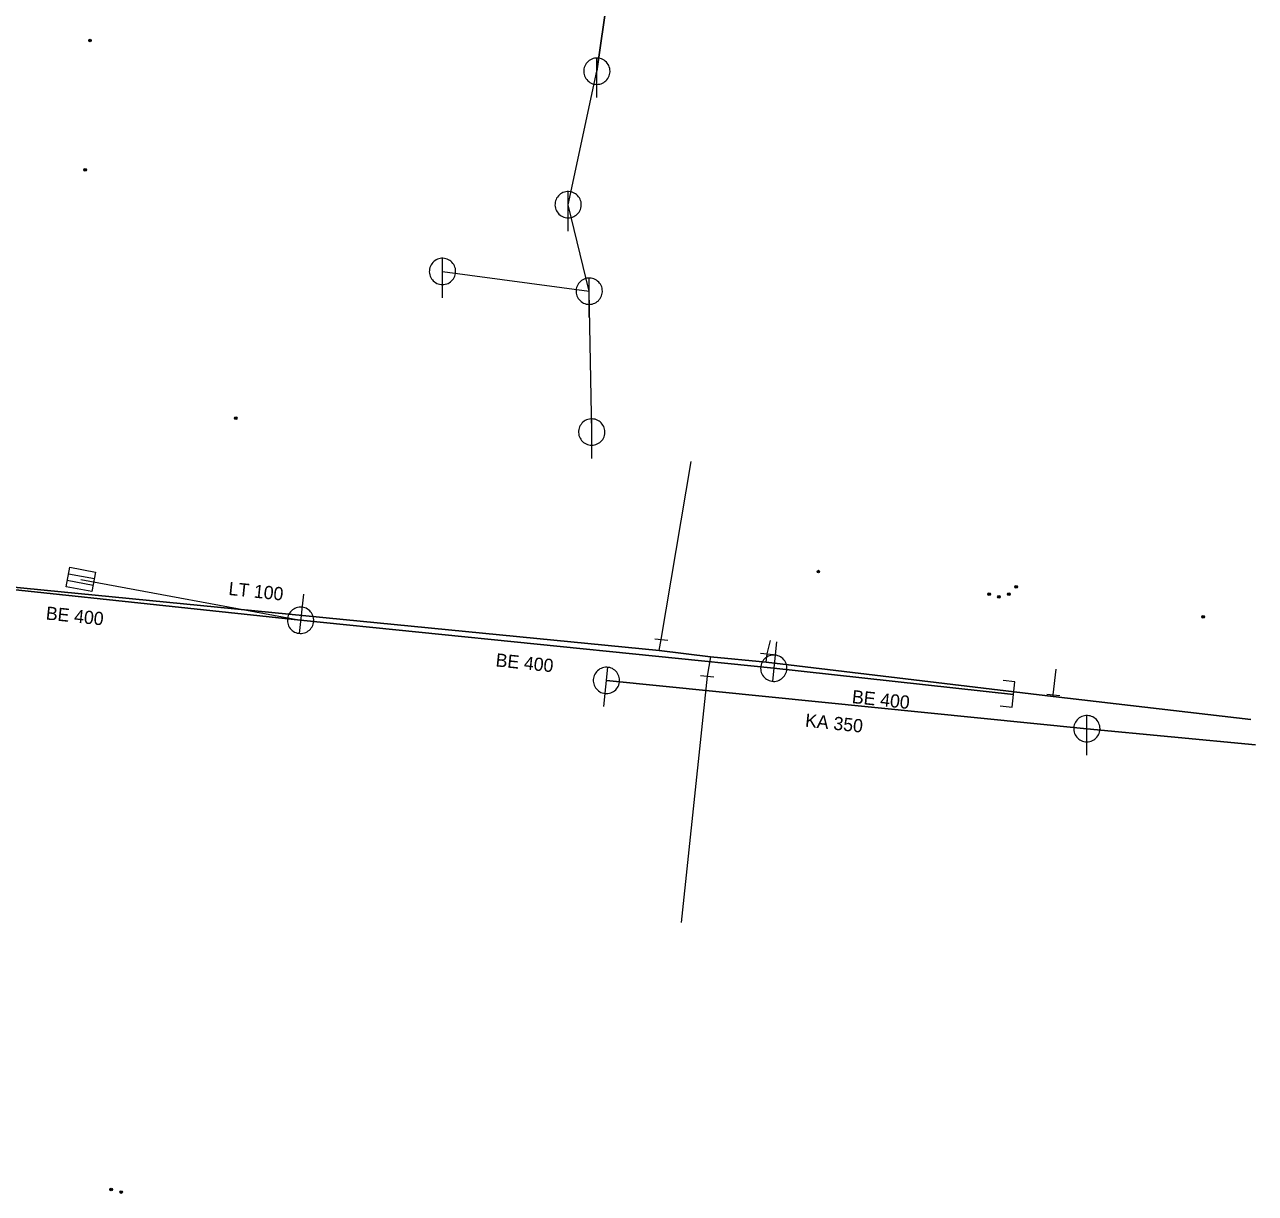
# Model space of a CAD drawing. Extents: x -783064 to -782702, y -1007904 to -1007145.
# Drawn here: x -782795.7 to -782702.3, y -1007715.2 to -1007626.6 of the extents above; entities that cross this region are included whole.
import ezdxf

# ---------------------------------------------------------------- set-up
doc = ezdxf.new("R2010")
doc.units = 0
doc.header["$LTSCALE"] = 0.4
doc.header["$PDMODE"] = 32
doc.header["$PDSIZE"] = 0.2
for name, color, linetype, lineweight in [('1', 7, 'Continuous', 13), ('11', 7, 'Continuous', 13), ('13', 7, 'Continuous', 13), ('14', 7, 'Continuous', 13), ('17', 7, 'Continuous', 25), ('22', 7, 'Continuous', 13), ('31', 7, 'Continuous', 13), ('34', 7, 'Continuous', 13)]:
    doc.layers.add(name, color=color, linetype=linetype, lineweight=lineweight)

msp = doc.modelspace()

# ---------------------------------------------------------------- linework, layer by layer
at = {"layer": '1'}
for p in [(-782790.73, -1007627.769), (-782791.09, -1007637.589), (-782779.67, -1007656.429), (-782735.449, -1007668.069), (-782722.489, -1007669.779), (-782720.989, -1007669.779), (-782720.44, -1007669.23), (-782721.739, -1007669.98), (-782706.239, -1007671.499), (-782789.12, -1007714.949), (-782788.37, -1007715.15)]:
    msp.add_point(p, dxfattribs=at)
at = {"layer": '11'}
for p, q in [((-782763.977, -1007645.291), (-782752.84, -1007646.79)), ((-782752.649, -1007657.48), (-782752.84, -1007646.79)), ((-782791.418, -1007668.667), (-782774.75, -1007671.763))]:
    msp.add_line(p, q, dxfattribs=at)
msp.add_lwpolyline([(-782752.84, -1007646.79), (-782754.44, -1007640.23), (-782752.26, -1007630.1)], dxfattribs=at)
at = {"layer": '13'}
for p, q in [((-782747.367, -1007673.212), (-782745.096, -1007659.704)), ((-782747.535, -1007674.052), (-782747.367, -1007673.212)), ((-782739.342, -1007674.299), (-782739.07, -1007673.309)), ((-782743.636, -1007674.53), (-782743.89, -1007676.004)), ((-782739.403, -1007674.936), (-782739.342, -1007674.299)), ((-782743.89, -1007676.004), (-782745.866, -1007694.699))]:
    msp.add_line(p, q, dxfattribs=at)
msp.add_lwpolyline([(-782717.631, -1007677.556), (-782717.616, -1007677.428), (-782717.401, -1007675.479)], dxfattribs=at)
at = {"layer": '14', "lineweight": 25}
for p, q in [((-782752.26, -1007630.1), (-782748.649, -1007604.55)), ((-782738.832, -1007675.401), (-782774.75, -1007671.763)), ((-782720.642, -1007677.385), (-782738.832, -1007675.401)), ((-782751.532, -1007676.327), (-782715.07, -1007679.99)), ((-782715.07, -1007679.99), (-782702.277, -1007681.219))]:
    msp.add_line(p, q, dxfattribs=at)
msp.add_lwpolyline([(-782774.75, -1007671.763), (-782807.095, -1007668.323), (-782809.579, -1007667.28)], dxfattribs=at)
at = {"layer": '17'}
msp.add_lwpolyline([(-782702.62, -1007679.29), (-782717.631, -1007677.556), (-782739.403, -1007674.936), (-782743.636, -1007674.53), (-782747.535, -1007674.052), (-782805.066, -1007668.425)], dxfattribs=at)
at = {"layer": '22'}
for p, q in [((-782752.26, -1007632.1), (-782752.259, -1007629.1)), ((-782754.44, -1007642.23), (-782754.439, -1007639.23)), ((-782763.977, -1007647.291), (-782763.976, -1007644.291)), ((-782752.84, -1007648.79), (-782752.839, -1007645.79)), ((-782752.649, -1007659.48), (-782752.648, -1007656.48)), ((-782792.456, -1007668.721), (-782790.49, -1007669.086)), ((-782792.365, -1007668.23), (-782790.398, -1007668.595)), ((-782774.538, -1007669.773), (-782774.855, -1007672.756)), ((-782738.63, -1007673.41), (-782738.932, -1007676.395)), ((-782751.731, -1007678.317), (-782751.432, -1007675.332)), ((-782715.07, -1007681.99), (-782715.069, -1007678.99))]:
    msp.add_line(p, q, dxfattribs=at)
for points in [[(-782751.26, -1007630.1), (-782751.265, -1007629.991), (-782751.283, -1007629.883), (-782751.313, -1007629.777), (-782751.353, -1007629.676), (-782751.405, -1007629.579), (-782751.467, -1007629.489), (-782751.539, -1007629.406), (-782751.619, -1007629.332), (-782751.707, -1007629.266), (-782751.801, -1007629.211), (-782751.901, -1007629.166), (-782752.006, -1007629.133), (-782752.113, -1007629.111), (-782752.222, -1007629.101), (-782752.332, -1007629.103), (-782752.44, -1007629.117), (-782752.547, -1007629.142), (-782752.65, -1007629.179), (-782752.748, -1007629.228), (-782752.84, -1007629.286), (-782752.926, -1007629.355), (-782753.003, -1007629.432), (-782753.072, -1007629.518), (-782753.131, -1007629.61), (-782753.179, -1007629.708), (-782753.216, -1007629.811), (-782753.242, -1007629.918), (-782753.256, -1007630.026), (-782753.259, -1007630.136), (-782753.249, -1007630.245), (-782753.228, -1007630.352), (-782753.194, -1007630.456), (-782753.15, -1007630.556), (-782753.095, -1007630.651), (-782753.029, -1007630.739), (-782752.955, -1007630.819), (-782752.872, -1007630.891), (-782752.782, -1007630.953), (-782752.686, -1007631.005), (-782752.584, -1007631.046), (-782752.479, -1007631.076), (-782752.371, -1007631.094), (-782752.261, -1007631.1), (-782752.152, -1007631.094), (-782752.044, -1007631.076), (-782751.939, -1007631.047), (-782751.837, -1007631.006), (-782751.74, -1007630.954), (-782751.65, -1007630.892), (-782751.567, -1007630.821), (-782751.492, -1007630.741), (-782751.427, -1007630.653), (-782751.371, -1007630.559), (-782751.327, -1007630.459), (-782751.293, -1007630.355), (-782751.271, -1007630.247), (-782751.261, -1007630.138)], [(-782753.44, -1007640.23), (-782753.445, -1007640.121), (-782753.463, -1007640.013), (-782753.493, -1007639.907), (-782753.533, -1007639.806), (-782753.585, -1007639.709), (-782753.647, -1007639.619), (-782753.719, -1007639.536), (-782753.799, -1007639.462), (-782753.887, -1007639.396), (-782753.981, -1007639.341), (-782754.081, -1007639.296), (-782754.186, -1007639.263), (-782754.293, -1007639.241), (-782754.402, -1007639.231), (-782754.512, -1007639.233), (-782754.62, -1007639.247), (-782754.727, -1007639.272), (-782754.83, -1007639.309), (-782754.928, -1007639.358), (-782755.02, -1007639.416), (-782755.106, -1007639.485), (-782755.183, -1007639.562), (-782755.252, -1007639.648), (-782755.311, -1007639.74), (-782755.359, -1007639.838), (-782755.396, -1007639.941), (-782755.422, -1007640.048), (-782755.436, -1007640.156), (-782755.439, -1007640.266), (-782755.429, -1007640.375), (-782755.408, -1007640.482), (-782755.374, -1007640.586), (-782755.33, -1007640.686), (-782755.275, -1007640.781), (-782755.209, -1007640.869), (-782755.135, -1007640.949), (-782755.052, -1007641.021), (-782754.962, -1007641.083), (-782754.866, -1007641.135), (-782754.764, -1007641.176), (-782754.659, -1007641.206), (-782754.551, -1007641.224), (-782754.441, -1007641.23), (-782754.332, -1007641.224), (-782754.224, -1007641.206), (-782754.119, -1007641.177), (-782754.017, -1007641.136), (-782753.92, -1007641.084), (-782753.83, -1007641.022), (-782753.747, -1007640.951), (-782753.672, -1007640.871), (-782753.607, -1007640.783), (-782753.551, -1007640.689), (-782753.507, -1007640.589), (-782753.473, -1007640.485), (-782753.451, -1007640.377), (-782753.441, -1007640.268)], [(-782762.977, -1007645.291), (-782762.982, -1007645.182), (-782763, -1007645.074), (-782763.03, -1007644.968), (-782763.07, -1007644.867), (-782763.122, -1007644.77), (-782763.184, -1007644.68), (-782763.256, -1007644.597), (-782763.336, -1007644.523), (-782763.424, -1007644.457), (-782763.518, -1007644.402), (-782763.618, -1007644.357), (-782763.723, -1007644.324), (-782763.83, -1007644.302), (-782763.939, -1007644.292), (-782764.049, -1007644.294), (-782764.157, -1007644.308), (-782764.264, -1007644.333), (-782764.367, -1007644.37), (-782764.465, -1007644.419), (-782764.557, -1007644.477), (-782764.643, -1007644.546), (-782764.72, -1007644.623), (-782764.789, -1007644.709), (-782764.848, -1007644.801), (-782764.896, -1007644.899), (-782764.933, -1007645.002), (-782764.959, -1007645.109), (-782764.973, -1007645.217), (-782764.976, -1007645.327), (-782764.966, -1007645.436), (-782764.945, -1007645.543), (-782764.911, -1007645.647), (-782764.867, -1007645.747), (-782764.812, -1007645.842), (-782764.746, -1007645.93), (-782764.672, -1007646.01), (-782764.589, -1007646.082), (-782764.499, -1007646.144), (-782764.403, -1007646.196), (-782764.301, -1007646.237), (-782764.196, -1007646.267), (-782764.088, -1007646.285), (-782763.978, -1007646.291), (-782763.869, -1007646.285), (-782763.761, -1007646.267), (-782763.656, -1007646.238), (-782763.554, -1007646.197), (-782763.457, -1007646.145), (-782763.367, -1007646.083), (-782763.284, -1007646.012), (-782763.209, -1007645.932), (-782763.144, -1007645.844), (-782763.088, -1007645.75), (-782763.044, -1007645.65), (-782763.01, -1007645.546), (-782762.988, -1007645.438), (-782762.978, -1007645.329)], [(-782751.84, -1007646.79), (-782751.845, -1007646.681), (-782751.863, -1007646.573), (-782751.893, -1007646.467), (-782751.933, -1007646.366), (-782751.985, -1007646.269), (-782752.047, -1007646.179), (-782752.119, -1007646.096), (-782752.199, -1007646.022), (-782752.287, -1007645.956), (-782752.381, -1007645.901), (-782752.481, -1007645.856), (-782752.586, -1007645.823), (-782752.693, -1007645.801), (-782752.802, -1007645.791), (-782752.912, -1007645.793), (-782753.02, -1007645.807), (-782753.127, -1007645.832), (-782753.23, -1007645.869), (-782753.328, -1007645.918), (-782753.42, -1007645.976), (-782753.506, -1007646.045), (-782753.583, -1007646.122), (-782753.652, -1007646.208), (-782753.711, -1007646.3), (-782753.759, -1007646.398), (-782753.796, -1007646.501), (-782753.822, -1007646.608), (-782753.836, -1007646.716), (-782753.839, -1007646.826), (-782753.829, -1007646.935), (-782753.808, -1007647.042), (-782753.774, -1007647.146), (-782753.73, -1007647.246), (-782753.675, -1007647.341), (-782753.609, -1007647.429), (-782753.535, -1007647.509), (-782753.452, -1007647.581), (-782753.362, -1007647.643), (-782753.266, -1007647.695), (-782753.164, -1007647.736), (-782753.059, -1007647.766), (-782752.951, -1007647.784), (-782752.841, -1007647.79), (-782752.732, -1007647.784), (-782752.624, -1007647.766), (-782752.519, -1007647.737), (-782752.417, -1007647.696), (-782752.32, -1007647.644), (-782752.23, -1007647.582), (-782752.147, -1007647.511), (-782752.072, -1007647.431), (-782752.007, -1007647.343), (-782751.951, -1007647.249), (-782751.907, -1007647.149), (-782751.873, -1007647.045), (-782751.851, -1007646.937), (-782751.841, -1007646.828)], [(-782751.649, -1007657.48), (-782751.654, -1007657.371), (-782751.672, -1007657.263), (-782751.702, -1007657.157), (-782751.742, -1007657.056), (-782751.794, -1007656.959), (-782751.856, -1007656.869), (-782751.928, -1007656.786), (-782752.008, -1007656.712), (-782752.096, -1007656.646), (-782752.19, -1007656.591), (-782752.29, -1007656.546), (-782752.395, -1007656.513), (-782752.502, -1007656.491), (-782752.611, -1007656.481), (-782752.721, -1007656.483), (-782752.829, -1007656.497), (-782752.936, -1007656.522), (-782753.039, -1007656.559), (-782753.137, -1007656.608), (-782753.229, -1007656.666), (-782753.315, -1007656.735), (-782753.392, -1007656.812), (-782753.461, -1007656.898), (-782753.52, -1007656.99), (-782753.568, -1007657.088), (-782753.605, -1007657.191), (-782753.631, -1007657.298), (-782753.645, -1007657.406), (-782753.648, -1007657.516), (-782753.638, -1007657.625), (-782753.617, -1007657.732), (-782753.583, -1007657.836), (-782753.539, -1007657.936), (-782753.484, -1007658.031), (-782753.418, -1007658.119), (-782753.344, -1007658.199), (-782753.261, -1007658.271), (-782753.171, -1007658.333), (-782753.075, -1007658.385), (-782752.973, -1007658.426), (-782752.868, -1007658.456), (-782752.76, -1007658.474), (-782752.65, -1007658.48), (-782752.541, -1007658.474), (-782752.433, -1007658.456), (-782752.328, -1007658.427), (-782752.226, -1007658.386), (-782752.129, -1007658.334), (-782752.039, -1007658.272), (-782751.956, -1007658.201), (-782751.881, -1007658.121), (-782751.816, -1007658.033), (-782751.76, -1007657.939), (-782751.716, -1007657.839), (-782751.682, -1007657.735), (-782751.66, -1007657.627), (-782751.65, -1007657.518)], [(-782792.273, -1007667.738), (-782790.307, -1007668.103), (-782790.581, -1007669.578), (-782792.547, -1007669.213)], [(-782775.744, -1007671.656), (-782775.749, -1007671.765), (-782775.743, -1007671.875), (-782775.724, -1007671.983), (-782775.695, -1007672.088), (-782775.654, -1007672.19), (-782775.602, -1007672.286), (-782775.539, -1007672.376), (-782775.467, -1007672.458), (-782775.387, -1007672.533), (-782775.299, -1007672.598), (-782775.204, -1007672.653), (-782775.103, -1007672.697), (-782774.999, -1007672.73), (-782774.892, -1007672.751), (-782774.782, -1007672.761), (-782774.673, -1007672.759), (-782774.564, -1007672.745), (-782774.458, -1007672.719), (-782774.355, -1007672.681), (-782774.258, -1007672.633), (-782774.165, -1007672.573), (-782774.08, -1007672.505), (-782774.003, -1007672.427), (-782773.934, -1007672.341), (-782773.876, -1007672.249), (-782773.828, -1007672.151), (-782773.791, -1007672.047), (-782773.766, -1007671.941), (-782773.752, -1007671.832), (-782773.751, -1007671.722), (-782773.76, -1007671.614), (-782773.783, -1007671.507), (-782773.816, -1007671.403), (-782773.861, -1007671.302), (-782773.917, -1007671.208), (-782773.982, -1007671.121), (-782774.057, -1007671.04), (-782774.14, -1007670.969), (-782774.23, -1007670.907), (-782774.327, -1007670.856), (-782774.428, -1007670.815), (-782774.534, -1007670.785), (-782774.643, -1007670.768), (-782774.752, -1007670.762), (-782774.861, -1007670.769), (-782774.969, -1007670.786), (-782775.074, -1007670.816), (-782775.176, -1007670.858), (-782775.272, -1007670.91), (-782775.362, -1007670.972), (-782775.445, -1007671.043), (-782775.519, -1007671.124), (-782775.585, -1007671.212), (-782775.639, -1007671.306), (-782775.684, -1007671.406), (-782775.717, -1007671.511), (-782775.739, -1007671.619)], [(-782739.826, -1007675.299), (-782739.831, -1007675.408), (-782739.824, -1007675.518), (-782739.805, -1007675.626), (-782739.776, -1007675.731), (-782739.734, -1007675.832), (-782739.681, -1007675.928), (-782739.618, -1007676.018), (-782739.546, -1007676.1), (-782739.465, -1007676.174), (-782739.377, -1007676.238), (-782739.282, -1007676.293), (-782739.181, -1007676.337), (-782739.076, -1007676.369), (-782738.969, -1007676.39), (-782738.859, -1007676.399), (-782738.75, -1007676.396), (-782738.641, -1007676.382), (-782738.535, -1007676.356), (-782738.433, -1007676.317), (-782738.335, -1007676.268), (-782738.243, -1007676.208), (-782738.159, -1007676.14), (-782738.081, -1007676.061), (-782738.013, -1007675.975), (-782737.956, -1007675.883), (-782737.908, -1007675.784), (-782737.872, -1007675.68), (-782737.847, -1007675.574), (-782737.834, -1007675.465), (-782737.833, -1007675.355), (-782737.843, -1007675.247), (-782737.866, -1007675.14), (-782737.9, -1007675.036), (-782737.945, -1007674.936), (-782738.002, -1007674.842), (-782738.068, -1007674.755), (-782738.143, -1007674.675), (-782738.226, -1007674.604), (-782738.316, -1007674.543), (-782738.414, -1007674.491), (-782738.515, -1007674.451), (-782738.621, -1007674.422), (-782738.73, -1007674.405), (-782738.839, -1007674.4), (-782738.948, -1007674.407), (-782739.055, -1007674.425), (-782739.161, -1007674.456), (-782739.263, -1007674.498), (-782739.359, -1007674.551), (-782739.448, -1007674.613), (-782739.531, -1007674.685), (-782739.604, -1007674.766), (-782739.67, -1007674.854), (-782739.724, -1007674.949), (-782739.768, -1007675.049), (-782739.801, -1007675.154), (-782739.822, -1007675.262)], [(-782750.537, -1007676.427), (-782750.532, -1007676.318), (-782750.539, -1007676.209), (-782750.558, -1007676.1), (-782750.588, -1007675.996), (-782750.63, -1007675.894), (-782750.682, -1007675.798), (-782750.746, -1007675.708), (-782750.818, -1007675.627), (-782750.899, -1007675.552), (-782750.987, -1007675.488), (-782751.082, -1007675.433), (-782751.183, -1007675.39), (-782751.287, -1007675.358), (-782751.395, -1007675.337), (-782751.505, -1007675.328), (-782751.613, -1007675.331), (-782751.722, -1007675.345), (-782751.829, -1007675.372), (-782751.931, -1007675.41), (-782752.028, -1007675.459), (-782752.121, -1007675.519), (-782752.205, -1007675.588), (-782752.282, -1007675.667), (-782752.35, -1007675.752), (-782752.408, -1007675.845), (-782752.455, -1007675.944), (-782752.491, -1007676.048), (-782752.516, -1007676.154), (-782752.529, -1007676.263), (-782752.53, -1007676.372), (-782752.52, -1007676.481), (-782752.496, -1007676.588), (-782752.463, -1007676.692), (-782752.417, -1007676.792), (-782752.361, -1007676.886), (-782752.295, -1007676.973), (-782752.22, -1007677.053), (-782752.136, -1007677.124), (-782752.046, -1007677.185), (-782751.948, -1007677.236), (-782751.847, -1007677.276), (-782751.741, -1007677.305), (-782751.632, -1007677.322), (-782751.523, -1007677.327), (-782751.414, -1007677.32), (-782751.307, -1007677.301), (-782751.201, -1007677.271), (-782751.1, -1007677.229), (-782751.004, -1007677.176), (-782750.914, -1007677.114), (-782750.831, -1007677.042), (-782750.758, -1007676.96), (-782750.693, -1007676.873), (-782750.639, -1007676.777), (-782750.595, -1007676.677), (-782750.562, -1007676.572), (-782750.541, -1007676.465)], [(-782714.07, -1007679.99), (-782714.075, -1007679.881), (-782714.093, -1007679.773), (-782714.123, -1007679.667), (-782714.163, -1007679.566), (-782714.215, -1007679.469), (-782714.277, -1007679.379), (-782714.349, -1007679.296), (-782714.429, -1007679.222), (-782714.517, -1007679.156), (-782714.611, -1007679.101), (-782714.711, -1007679.056), (-782714.816, -1007679.023), (-782714.923, -1007679.001), (-782715.032, -1007678.991), (-782715.142, -1007678.993), (-782715.25, -1007679.007), (-782715.357, -1007679.032), (-782715.46, -1007679.069), (-782715.558, -1007679.118), (-782715.65, -1007679.176), (-782715.736, -1007679.245), (-782715.813, -1007679.322), (-782715.882, -1007679.408), (-782715.941, -1007679.5), (-782715.989, -1007679.598), (-782716.026, -1007679.701), (-782716.052, -1007679.808), (-782716.066, -1007679.916), (-782716.069, -1007680.026), (-782716.059, -1007680.135), (-782716.038, -1007680.242), (-782716.004, -1007680.346), (-782715.96, -1007680.446), (-782715.905, -1007680.541), (-782715.839, -1007680.629), (-782715.765, -1007680.709), (-782715.682, -1007680.781), (-782715.592, -1007680.843), (-782715.496, -1007680.895), (-782715.394, -1007680.936), (-782715.289, -1007680.966), (-782715.181, -1007680.984), (-782715.071, -1007680.99), (-782714.962, -1007680.984), (-782714.854, -1007680.966), (-782714.749, -1007680.937), (-782714.647, -1007680.896), (-782714.55, -1007680.844), (-782714.46, -1007680.782), (-782714.377, -1007680.711), (-782714.302, -1007680.631), (-782714.237, -1007680.543), (-782714.181, -1007680.449), (-782714.137, -1007680.349), (-782714.103, -1007680.245), (-782714.081, -1007680.137), (-782714.071, -1007680.028)]]:
    msp.add_lwpolyline(points, close=True, dxfattribs=at)
at = {"layer": '31'}
msp.add_lwpolyline([(-782721.641, -1007678.247), (-782720.746, -1007678.345), (-782720.536, -1007676.424), (-782721.432, -1007676.327)], dxfattribs=at)
at = {"layer": '34'}
for p, q in [((-782747.864, -1007673.163), (-782746.869, -1007673.261)), ((-782739.839, -1007674.25), (-782738.844, -1007674.348)), ((-782744.387, -1007675.955), (-782743.392, -1007676.053)), ((-782718.113, -1007677.379), (-782717.118, -1007677.477))]:
    msp.add_line(p, q, dxfattribs=at)

# ---------------------------------------------------------------- texts
at = {"layer": '1'}
for s, p in [('LT 100', (-782780.25, -1007669.837)), ('BE 400', (-782794.115, -1007671.699)), ('BE 400', (-782759.976, -1007675.255)), ('BE 400', (-782732.934, -1007678.041)), ('KA 350', (-782736.483, -1007679.833))]:
    msp.add_text(s, height=1, rotation=354, dxfattribs=at).set_placement(p)

doc.saveas('drawing.dxf')
